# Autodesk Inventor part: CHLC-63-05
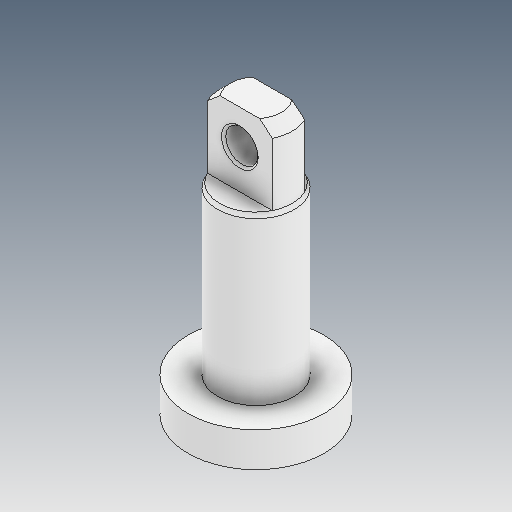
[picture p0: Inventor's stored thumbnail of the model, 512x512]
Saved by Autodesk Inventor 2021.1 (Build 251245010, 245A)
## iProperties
Created: 2021-05
Part Number: CHLC-63-05
Material: Ogólny
Document SubType Name: Modeling
Designer: user
Density: 1 g/cm^3
Appearance: Domyślna
Author: user
Revision Number: ÈÎºÎ
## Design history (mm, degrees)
feature "µ¹½Ç2"
node "Bryła1"
